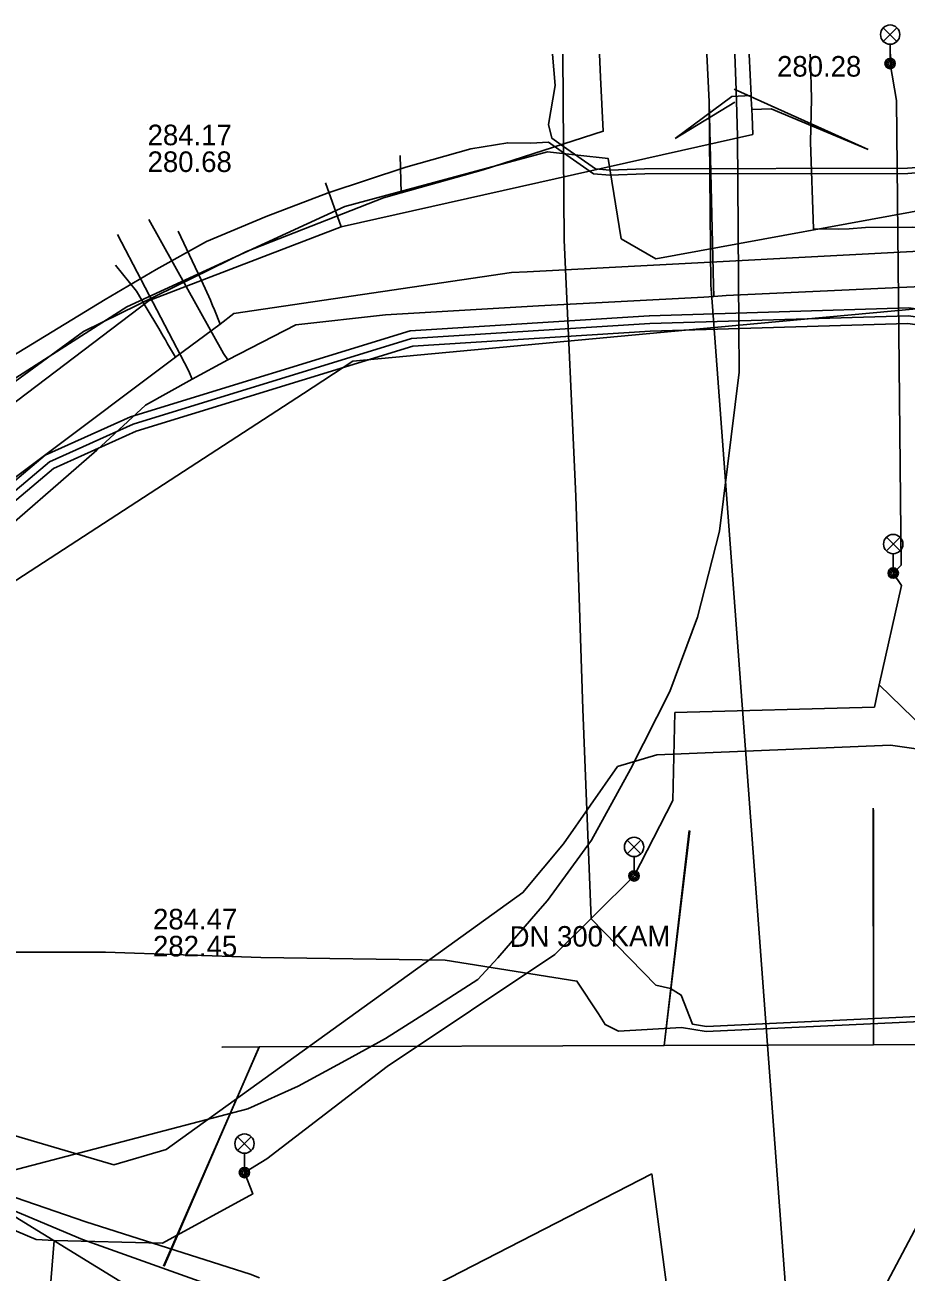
# Model space of a CAD drawing. Extents: x -599854 to -599675, y -1160809 to -1160543.
# Drawn here: x -599799.9 to -599765.66, y -1160591.29 to -1160542.82 of the extents above; entities that cross this region are included whole.
import ezdxf

# ---------------------------------------------------------------- set-up
doc = ezdxf.new("R2010")
doc.units = 0
for name, color, linetype in [('BKOM-ODVODNENI_trasa sítě', 7, 'Continuous'), ('BVK-JEDNOTNA_popisy', 7, 'Continuous'), ('BVK-JEDNOTNA_trasa sítě', 7, 'Continuous'), ('BVK-KANALIZACE_ vyřazená trasa sítě', 7, 'Continuous'), ('BVK-VODOVOD_trasa sítě', 7, 'Continuous'), ('BVK-VODOVOD_trasa zrušené sítě', 7, 'Continuous'), ('CETIN_kabel podzemní', 7, 'Continuous'), ('CETIN_kabel podzemní neprovozovaný', 7, 'Continuous'), ('DESTOVA-NEPROVOZOVANA_popisy', 7, 'Continuous'), ('DESTOVA_trasa neprovozované sítě', 7, 'Continuous'), ('DPMB_kabel', 7, 'Continuous'), ('DPMB_kyneta', 7, 'Continuous'), ('DPMB_trolejové vedení-nosné lano', 7, 'Continuous'), ('DSP-JEDNOTNA-BVK_trasa sítě', 7, 'Continuous'), ('EON-NN_kabel', 7, 'Continuous'), ('EON-NN_kabel zrušené sítě', 7, 'Continuous'), ('INNOGY-NTL_trasa sítě', 7, 'Continuous'), ('INNOGY-STL_trasa sítě', 7, 'Continuous'), ('JEDNOTNA-NEPR_popisy', 7, 'Continuous'), ('JEDNOTNA_trasa neprovozované sítě', 7, 'Continuous'), ('TSB_kabel VO', 7, 'Continuous'), ('TSB_lampy VO', 7, 'Continuous')]:
    doc.layers.add(name, color=color, linetype=linetype)

msp = doc.modelspace()

# ---------------------------------------------------------------- linework, layer by layer
at = {"layer": 'BKOM-ODVODNENI_trasa sítě'}
for points in [[(-599767.13, -1160547.66), (-599772.336, -1160545.322)], [(-599774.63, -1160547.23), (-599772.315, -1160545.821)], [(-599766.926, -1160573.322), (-599766.92, -1160582.45)], [(-599774.061, -1160574.134), (-599775.06, -1160582.48)], [(-599792.21, -1160582.54), (-599790.8, -1160582.535), (-599775.06, -1160582.479), (-599766.92, -1160582.451), (-599752.61, -1160582.4)], [(-599794.512, -1160591.061), (-599790.8, -1160582.54)]]:
    msp.add_lwpolyline(points, dxfattribs=at)
at = {"layer": 'BVK-JEDNOTNA_trasa sítě'}
msp.add_lwpolyline([(-599771.61, -1160547.08), (-599771.647, -1160546.364), (-599771.66, -1160546.11), (-599771.675, -1160545.698), (-599771.68, -1160545.56), (-599771.7591, -1160543.9495)], dxfattribs=at)
at = {"layer": 'BVK-KANALIZACE_ vyřazená trasa sítě'}
for points in [[(-599772.213, -1160547.139), (-599772.256, -1160545.785), (-599772.269, -1160545.352), (-599772.3132, -1160543.9495)], [(-599781.529, -1160579.068), (-599779.972, -1160577.276), (-599779.597, -1160576.845), (-599777.887, -1160574.498), (-599776.366, -1160571.74), (-599774.84, -1160568.724), (-599773.766, -1160565.837), (-599772.907, -1160562.49), (-599772.14, -1160556.317), (-599772.154, -1160554.529), (-599772.199, -1160548.939), (-599772.213, -1160547.139)], [(-599822.796, -1160585.73), (-599821.384, -1160585.908), (-599811.025, -1160587.485), (-599805.422, -1160587.8), (-599801.54, -1160587.634), (-599791.243, -1160584.941), (-599789.279, -1160584.062), (-599787.442, -1160583.059), (-599785.884, -1160582.21), (-599784.335, -1160581.226), (-599782.303, -1160579.92), (-599781.529, -1160579.068)]]:
    msp.add_lwpolyline(points, dxfattribs=at)
at = {"layer": 'BVK-VODOVOD_trasa sítě'}
for p, q in [((-599773.15, -1160552.95), (-599773.31, -1160545.81)), ((-599773.129, -1160553.369), (-599773.52, -1160553.4)), ((-599773.129, -1160553.369), (-599773.15, -1160552.95)), ((-599772.65, -1160553.34), (-599773.129, -1160553.369))]:
    msp.add_line(p, q, dxfattribs=at)
for points in [[(-599773.31, -1160545.81), (-599773.406, -1160543.9495)], [(-599792.01, -1160555.84), (-599792.18, -1160555.59), (-599795.084, -1160550.381)], [(-599793.4, -1160556.58), (-599793.55, -1160556.25), (-599796.307, -1160550.968)], [(-599719.633, -1160602.967), (-599720.5, -1160603.21), (-599721.46, -1160603.05), (-599723.09, -1160601.91), (-599724.27, -1160595.77), (-599725.34, -1160590.19), (-599725.75, -1160588.02), (-599726.33, -1160585.11), (-599727.19, -1160580.77), (-599730.66, -1160575.71), (-599731.23, -1160574.92), (-599731.73, -1160574.22), (-599732.69, -1160572.85), (-599736.99, -1160566.71), (-599739.23, -1160561.6), (-599744.81, -1160557.63), (-599749.37, -1160554.46), (-599750.43, -1160553.69), (-599750.93, -1160553.31), (-599752.19, -1160552.51), (-599757.77, -1160552.65), (-599772.65, -1160553.34)], [(-599773.52, -1160553.4), (-599779.95, -1160553.74), (-599785.89, -1160554.08), (-599789.37, -1160554.47), (-599792.01, -1160555.84), (-599793.4, -1160556.58), (-599795.21, -1160557.59), (-599797.11, -1160559.34), (-599801.61, -1160563.26), (-599803.76, -1160565.39), (-599806.64, -1160570.9), (-599807.42, -1160572.3), (-599808.48, -1160574.16), (-599810.38, -1160577.75), (-599811.83, -1160580.4), (-599815.36, -1160586.95)]]:
    msp.add_lwpolyline(points, dxfattribs=at)
at = {"layer": 'BVK-VODOVOD_trasa zrušené sítě'}
for points in [[(-599773.31, -1160545.81), (-599773.4008, -1160543.9495)], [(-599769.661, -1160601.069), (-599773.22, -1160553.25), (-599773.248, -1160552.933), (-599773.31, -1160545.81)], [(-599723.312, -1160596.189), (-599723.552, -1160595.075), (-599725.385, -1160585.124), (-599727.088, -1160577.648), (-599730.061, -1160573.561), (-599730.185, -1160573.396), (-599730.663, -1160572.731), (-599734.747, -1160567.144), (-599747.147, -1160556.314), (-599750.794, -1160554.698), (-599754.863, -1160552.892), (-599773.118, -1160554.584), (-599787.156, -1160555.886), (-599789.075, -1160557.142), (-599798.149, -1160563.04), (-599806.144, -1160568.237), (-599808.168, -1160571.846), (-599815.66, -1160586.425), (-599816.228, -1160587.481)]]:
    msp.add_lwpolyline(points, dxfattribs=at)
at = {"layer": 'CETIN_kabel podzemní'}
for points in [[(-599760.54, -1160548.25), (-599763.79, -1160549.79), (-599775.39, -1160551.91), (-599776.73, -1160551.13), (-599777.24, -1160548.01), (-599779.6, -1160547.75), (-599787.47, -1160549.87), (-599795.94, -1160553.78), (-599800.44, -1160556.65), (-599809.68, -1160565.19), (-599817.48, -1160577.77), (-599818.39, -1160579.19)], [(-599814.4, -1160581.07), (-599811.3, -1160581.33), (-599803.39, -1160585.07), (-599799.44, -1160586.24), (-599796.45, -1160587.12), (-599794.41, -1160586.52), (-599780.55, -1160576.54), (-599778.97, -1160574.64), (-599776.87, -1160571.64), (-599775.34, -1160571.18), (-599766.27, -1160570.81), (-599760.94, -1160571.57), (-599759.27, -1160573.58), (-599754.54, -1160576.32), (-599750.34, -1160581.07), (-599747.4, -1160585.47), (-599742.37, -1160594.32)]]:
    msp.add_lwpolyline(points, dxfattribs=at)
at = {"layer": 'CETIN_kabel podzemní neprovozovaný'}
for points in [[(-599785.28, -1160549.34), (-599782.1, -1160548.45), (-599777.43, -1160546.95), (-599777.53, -1160544.85), (-599777.5746, -1160543.9495)], [(-599785.32, -1160547.9), (-599785.28, -1160549.34)], [(-599785.97, -1160549.54), (-599785.28, -1160549.34)], [(-599806.6, -1160561.96), (-599804.15, -1160559.5), (-599797.63, -1160554.73), (-599791.29, -1160551.62), (-599785.97, -1160549.54)], [(-599812.02, -1160583.41), (-599810.64, -1160583.64), (-599808.92, -1160584.27), (-599805.91, -1160586), (-599802.25, -1160587.71), (-599797.54, -1160589.34), (-599791.15, -1160591.37), (-599790.79, -1160591.51)], [(-599811.253, -1160583.779), (-599802.42, -1160588.03), (-599797.67, -1160590.02), (-599791.5, -1160592.22), (-599791.17, -1160592.27)]]:
    msp.add_lwpolyline(points, dxfattribs=at)
at = {"layer": 'DESTOVA-NEPROVOZOVANA_popisy'}
msp.add_line((-599794.923, -1160579.019), (-599794.923, -1160579.019), dxfattribs=at)
at = {"layer": 'DESTOVA_trasa neprovozované sítě'}
for p, q in [((-599788.22, -1160548.96), (-599787.61, -1160550.66)), ((-599766.94, -1160573.26), (-599766.92, -1160582.451)), ((-599774.09, -1160574.12), (-599775.06, -1160582.479)), ((-599794.49, -1160591.06), (-599790.8, -1160582.535))]:
    msp.add_line(p, q, dxfattribs=at)
for points in [[(-599774.63, -1160547.23), (-599772.433, -1160545.599), (-599771.68, -1160545.56)], [(-599767.13, -1160547.66), (-599770.908, -1160546.077), (-599771.66, -1160546.11)], [(-599792.25, -1160582.55), (-599790.8, -1160582.535), (-599775.06, -1160582.479), (-599766.92, -1160582.451), (-599752.61, -1160582.4)]]:
    msp.add_lwpolyline(points, dxfattribs=at)
at = {"layer": 'DPMB_kabel'}
for points in [[(-599742.967, -1160562.458), (-599745.93, -1160559.394), (-599753.706, -1160555.543), (-599765.553, -1160553.819), (-599775.629, -1160554.12), (-599775.639, -1160554.121), (-599784.934, -1160554.703), (-599795.796, -1160558.049), (-599799.111, -1160559.544), (-599805.518, -1160564.943)], [(-599742.967, -1160562.458), (-599745.93, -1160559.394), (-599753.706, -1160555.543), (-599765.553, -1160553.819), (-599775.629, -1160554.12), (-599775.639, -1160554.121), (-599784.934, -1160554.703), (-599795.796, -1160558.049), (-599799.111, -1160559.544), (-599805.518, -1160564.943)], [(-599854.3744, -1160570.8811), (-599853.98, -1160571.11), (-599853.34, -1160571.94), (-599850.41, -1160575.09), (-599849.54, -1160575.55), (-599841.94, -1160567.75), (-599841.46, -1160567.86), (-599836.83, -1160571.43), (-599830.31, -1160574.99), (-599826.68, -1160574.81), (-599821.59, -1160577.6), (-599817.92, -1160579.72), (-599816.48, -1160579.55), (-599815.751, -1160578.652), (-599810.91, -1160571.26), (-599805.31, -1160565.16), (-599798.95, -1160559.8), (-599795.69, -1160558.33), (-599784.88, -1160555), (-599775.62, -1160554.42), (-599765.57, -1160554.12), (-599753.796, -1160555.833), (-599746.11, -1160559.64), (-599743.15, -1160562.7)], [(-599854.3744, -1160570.8811), (-599853.98, -1160571.11), (-599853.34, -1160571.94), (-599850.41, -1160575.09), (-599849.54, -1160575.55), (-599841.94, -1160567.75), (-599841.46, -1160567.86), (-599836.83, -1160571.43), (-599830.31, -1160574.99), (-599826.68, -1160574.81), (-599821.59, -1160577.6), (-599817.92, -1160579.72), (-599816.48, -1160579.55), (-599815.751, -1160578.652), (-599810.91, -1160571.26), (-599805.31, -1160565.16), (-599798.95, -1160559.8), (-599795.69, -1160558.33), (-599784.88, -1160555), (-599775.62, -1160554.42), (-599765.57, -1160554.12), (-599753.796, -1160555.833), (-599746.11, -1160559.64), (-599743.15, -1160562.7)]]:
    msp.add_lwpolyline(points, dxfattribs=at)
at = {"layer": 'DPMB_kyneta'}
for points in [[(-599775.601, -1160554.719), (-599784.826, -1160555.297), (-599795.584, -1160558.611), (-599798.789, -1160560.056), (-599805.102, -1160565.377), (-599810.672, -1160571.445), (-599815.508, -1160578.829), (-599816.324, -1160579.834), (-599817.984, -1160580.03), (-599821.737, -1160577.861), (-599826.75, -1160575.114), (-599830.38, -1160575.294), (-599836.994, -1160571.682), (-599841.591, -1160568.138), (-599841.843, -1160568.08), (-599849.482, -1160575.92), (-599850.595, -1160575.331), (-599853.569, -1160572.134), (-599854.182, -1160571.34), (-599854.3744, -1160571.2283)], [(-599679.2237, -1160588.7865), (-599682.09, -1160589.515), (-599685.576, -1160587.065), (-599686.493, -1160586.917), (-599689.402, -1160587.72), (-599697.166, -1160589.741), (-599712.717, -1160593.601), (-599718.397, -1160595.039), (-599721.496, -1160595.147), (-599723.319, -1160593.689), (-599724.625, -1160587.968), (-599724.995, -1160585.706), (-599726.218, -1160580.085), (-599729.152, -1160573.2), (-599732.987, -1160568.044), (-599737.527, -1160565.171), (-599740.396, -1160564.524), (-599743.333, -1160562.942), (-599746.29, -1160559.886), (-599753.886, -1160556.123), (-599765.587, -1160554.421), (-599775.611, -1160554.72)]]:
    msp.add_lwpolyline(points, dxfattribs=at)
at = {"layer": 'DPMB_trolejové vedení-nosné lano'}
for points in [[(-599791.2, -1160594.72), (-599809.14, -1160583.7)], [(-599789.88, -1160594.84), (-599775.54, -1160587.47)], [(-599775.54, -1160587.47), (-599773.84, -1160600.3)]]:
    msp.add_lwpolyline(points, dxfattribs=at)
at = {"layer": 'DSP-JEDNOTNA-BVK_trasa sítě'}
for p, q in [((-599772.433, -1160545.599), (-599771.684, -1160545.563)), ((-599770.908, -1160546.077), (-599771.657, -1160546.112)), ((-599766.94, -1160573.26), (-599766.92, -1160582.451)), ((-599774.09, -1160574.12), (-599775.06, -1160582.479)), ((-599790.8, -1160582.535), (-599775.06, -1160582.479)), ((-599775.06, -1160582.479), (-599766.92, -1160582.451)), ((-599766.92, -1160582.451), (-599752.61, -1160582.4)), ((-599794.49, -1160591.06), (-599790.8, -1160582.535)), ((-599792.21, -1160582.54), (-599790.8, -1160582.535))]:
    msp.add_line(p, q, dxfattribs=at)
at = {"layer": 'EON-NN_kabel'}
for points in [[(-599779.292, -1160545.175), (-599779.3939, -1160543.9495)], [(-599762.627, -1160545.843), (-599762.668, -1160546.074), (-599762.734, -1160546.449), (-599762.827, -1160546.981), (-599763.401, -1160547.905), (-599764.06, -1160548.272), (-599764.861, -1160548.333), (-599765.604, -1160548.39), (-599775.822, -1160548.41), (-599777.168, -1160548.46), (-599777.735, -1160548.413), (-599778.972, -1160547.542), (-599779.425, -1160547.223), (-599779.55, -1160546.69), (-599779.292, -1160545.175)], [(-599762.43, -1160545.88), (-599762.48, -1160546.163), (-599762.636, -1160547.054), (-599763.259, -1160548.055), (-599764, -1160548.468), (-599764.843, -1160548.532), (-599765.596, -1160548.59), (-599775.818, -1160548.61), (-599777.172, -1160548.66), (-599777.805, -1160548.607), (-599778.97, -1160547.788), (-599779.554, -1160547.378), (-599780.24, -1160547.41), (-599781.14, -1160547.4), (-599782.57, -1160547.64), (-599785.1, -1160548.35), (-599788.12, -1160549.35), (-599790.53, -1160550.26), (-599792.84, -1160551.23), (-599794.8, -1160552.33), (-599796.78, -1160553.49), (-599801.45, -1160556.33)]]:
    msp.add_lwpolyline(points, dxfattribs=at)
at = {"layer": 'EON-NN_kabel zrušené sítě'}
for points in [[(-599778.9929, -1160543.9495), (-599778.972, -1160547.542), (-599778.97, -1160547.788), (-599778.95, -1160551.18), (-599778.49, -1160561.13), (-599778.22, -1160569.41), (-599777.9, -1160577.56), (-599775.38, -1160580.14), (-599774.82, -1160580.27), (-599774.4, -1160580.52), (-599773.962, -1160581.651), (-599773.414, -1160581.74), (-599764.965, -1160581.343), (-599764.621, -1160580.237), (-599764.322, -1160579.771), (-599762.931, -1160579.512), (-599762.188, -1160579.659), (-599761.325, -1160579.531)], [(-599761.295, -1160579.729), (-599762.192, -1160579.861), (-599762.969, -1160579.708), (-599764.198, -1160579.949), (-599764.439, -1160580.323), (-599764.815, -1160581.537), (-599773.426, -1160581.94), (-599774.387, -1160581.787), (-599776.84, -1160581.93), (-599777.35, -1160581.67), (-599777.61, -1160581.25), (-599778.45, -1160579.98), (-599783.57, -1160579.17), (-599790.74, -1160579.06), (-599796.77, -1160578.86), (-599802.11, -1160578.86)]]:
    msp.add_lwpolyline(points, dxfattribs=at)
at = {"layer": 'INNOGY-NTL_trasa sítě'}
for points in [[(-599769.3869, -1160543.9495), (-599769.379, -1160544.191), (-599769.33, -1160545.69), (-599769.376, -1160547.382), (-599769.259, -1160550.742), (-599768.28, -1160550.753)], [(-599762.899, -1160550.371), (-599762.79, -1160550.72), (-599764.29, -1160550.8), (-599765.418, -1160550.679), (-599767.231, -1160550.694), (-599767.869, -1160550.747), (-599768.28, -1160550.753)]]:
    msp.add_lwpolyline(points, dxfattribs=at)
at = {"layer": 'INNOGY-STL_trasa sítě'}
for points in [[(-599792.31, -1160554.45), (-599792.54, -1160553.89), (-599792.59, -1160553.78), (-599792.6, -1160553.76), (-599792.69, -1160553.52), (-599793.04, -1160552.75), (-599793.4, -1160551.99), (-599793.95, -1160550.84)], [(-599761.73, -1160551.43), (-599762.21, -1160551.46), (-599780.39, -1160552.41), (-599780.99, -1160552.44)], [(-599794.05, -1160555.73), (-599794.36, -1160555.21), (-599794.44, -1160555.06), (-599794.53, -1160554.92), (-599794.7, -1160554.62), (-599795.19, -1160553.8), (-599795.57, -1160553.17), (-599796.38, -1160552.15)], [(-599780.99, -1160552.44), (-599791.78, -1160554.03), (-599792.31, -1160554.45), (-599794.05, -1160555.73), (-599804.4, -1160563.49), (-599804.53, -1160563.48), (-599804.66, -1160563.47), (-599805.49, -1160563.4), (-599806.68, -1160563.29), (-599806.84, -1160563.28), (-599811.27, -1160567.47), (-599811.2, -1160567.91), (-599811.17, -1160568.07), (-599811.12, -1160568.36), (-599810.84, -1160570.05), (-599810.7, -1160570.94), (-599810.69, -1160571.01), (-599810.61, -1160571.46), (-599810.57, -1160571.72), (-599813.95, -1160577.93), (-599814.51, -1160578.96)]]:
    msp.add_lwpolyline(points, dxfattribs=at)
at = {"layer": 'JEDNOTNA-NEPR_popisy'}
msp.add_line((-599795.134, -1160546.695), (-599795.134, -1160546.695), dxfattribs=at)
at = {"layer": 'JEDNOTNA_trasa neprovozované sítě'}
msp.add_line((-599787.61, -1160550.66), (-599771.61, -1160547.08), dxfattribs=at)
msp.add_lwpolyline([(-599802.92, -1160559.49), (-599800.171, -1160557.403), (-599795.07, -1160553.53), (-599787.61, -1160550.66)], dxfattribs=at)
at = {"layer": 'TSB_kabel VO'}
for points in [[(-599766.2621, -1160543.9495), (-599766.24, -1160544.4)], [(-599766.28, -1160544.32), (-599766.03, -1160545.76), (-599765.85, -1160563.81), (-599766.16, -1160564.12), (-599765.84, -1160564.6), (-599766.71, -1160568.47)], [(-599854.3744, -1160555.1902), (-599854.04, -1160555.5), (-599849.6, -1160560.93), (-599846.5, -1160564.23), (-599842.34, -1160567.41), (-599836.14, -1160572.72), (-599835.53, -1160572.87), (-599830.9, -1160574.94), (-599826.66, -1160576.79), (-599812.72, -1160583.91), (-599805.44, -1160587.49), (-599799.47, -1160590.02), (-599798.76, -1160590.06), (-599794.55, -1160590.16), (-599791.05, -1160588.25), (-599791.37, -1160587.42), (-599790.5, -1160586.88), (-599785.83, -1160583.3), (-599779.31, -1160578.94), (-599776.23, -1160575.89), (-599774.72, -1160572.96), (-599774.64, -1160569.54), (-599766.89, -1160569.33), (-599766.71, -1160568.47)], [(-599766.71, -1160568.47), (-599766.89, -1160569.33), (-599774.64, -1160569.54), (-599774.72, -1160572.96), (-599776.23, -1160575.89), (-599779.31, -1160578.94), (-599785.83, -1160583.3), (-599790.5, -1160586.88), (-599791.37, -1160587.42), (-599791.05, -1160588.25), (-599794.55, -1160590.16), (-599798.76, -1160590.06), (-599799.72, -1160601.87), (-599800.78, -1160601.67)], [(-599766.71, -1160568.47), (-599762.32, -1160572.73), (-599758.16, -1160577.35), (-599760.07, -1160579.7), (-599764.277, -1160587.66), (-599769.44, -1160597.43)], [(-599712.85, -1160612.2), (-599713.231, -1160610.818), (-599715.05, -1160611.32), (-599720.13, -1160612.91), (-599729.8, -1160616.03), (-599730.26, -1160617.21), (-599734.33, -1160617.68), (-599739.29, -1160617.63), (-599739.48, -1160618.61), (-599740.14, -1160618.47), (-599744.95, -1160617.17), (-599744.01, -1160615.53), (-599741.64, -1160607.33), (-599740.03, -1160599.74), (-599742.84, -1160597.94), (-599743.59, -1160597.21), (-599749.46, -1160587.62), (-599756.62, -1160578.69), (-599758.16, -1160577.35), (-599762.32, -1160572.73), (-599766.71, -1160568.47)]]:
    msp.add_lwpolyline(points, dxfattribs=at)
at = {"layer": 'TSB_lampy VO'}
for p, q in [((-599766.545, -1160543.46), (-599766.015, -1160542.93)), ((-599766.545, -1160542.93), (-599766.015, -1160543.46)), ((-599766.545, -1160543.46), (-599766.015, -1160542.93)), ((-599766.545, -1160542.93), (-599766.015, -1160543.46)), ((-599766.28, -1160543.57), (-599766.28, -1160544.32)), ((-599766.28, -1160543.57), (-599766.28, -1160544.32)), ((-599766.425, -1160563.26), (-599765.895, -1160562.73)), ((-599766.425, -1160562.73), (-599765.895, -1160563.26)), ((-599766.425, -1160563.26), (-599765.895, -1160562.73)), ((-599766.425, -1160562.73), (-599765.895, -1160563.26)), ((-599766.16, -1160563.37), (-599766.16, -1160564.12)), ((-599766.16, -1160563.37), (-599766.16, -1160564.12)), ((-599776.495, -1160575.03), (-599775.965, -1160574.5)), ((-599776.495, -1160574.5), (-599775.965, -1160575.03)), ((-599776.495, -1160575.03), (-599775.965, -1160574.5)), ((-599776.495, -1160574.5), (-599775.965, -1160575.03)), ((-599776.23, -1160575.14), (-599776.23, -1160575.89)), ((-599776.23, -1160575.14), (-599776.23, -1160575.89)), ((-599791.635, -1160586.56), (-599791.105, -1160586.03)), ((-599791.635, -1160586.03), (-599791.105, -1160586.56)), ((-599791.635, -1160586.56), (-599791.105, -1160586.03)), ((-599791.635, -1160586.03), (-599791.105, -1160586.56)), ((-599791.37, -1160586.67), (-599791.37, -1160587.42)), ((-599791.37, -1160586.67), (-599791.37, -1160587.42))]:
    msp.add_line(p, q, dxfattribs=at)
for centre, radius in [((-599766.28, -1160543.195), 0.375), ((-599766.28, -1160543.195), 0.375), ((-599766.28, -1160544.32), 0.2), ((-599766.28, -1160544.32), 0.2), ((-599766.28, -1160544.32), 0.1445), ((-599766.28, -1160544.32), 0.1445), ((-599766.28, -1160544.32), 0.0876), ((-599766.28, -1160544.32), 0.0876), ((-599766.16, -1160562.995), 0.375), ((-599766.16, -1160562.995), 0.375), ((-599766.16, -1160564.12), 0.2), ((-599766.16, -1160564.12), 0.2), ((-599766.16, -1160564.12), 0.1445), ((-599766.16, -1160564.12), 0.1445), ((-599766.16, -1160564.12), 0.0876), ((-599766.16, -1160564.12), 0.0876), ((-599776.23, -1160574.765), 0.375), ((-599776.23, -1160574.765), 0.375), ((-599776.23, -1160575.89), 0.2), ((-599776.23, -1160575.89), 0.2), ((-599776.23, -1160575.89), 0.1445), ((-599776.23, -1160575.89), 0.1445), ((-599776.23, -1160575.89), 0.0876), ((-599776.23, -1160575.89), 0.0876), ((-599791.37, -1160586.295), 0.375), ((-599791.37, -1160586.295), 0.375), ((-599791.37, -1160587.42), 0.2), ((-599791.37, -1160587.42), 0.2), ((-599791.37, -1160587.42), 0.1445), ((-599791.37, -1160587.42), 0.1445), ((-599791.37, -1160587.42), 0.0876), ((-599791.37, -1160587.42), 0.0876)]:
    msp.add_circle(centre, radius, dxfattribs=at)

# ---------------------------------------------------------------- texts
at = {"layer": 'BVK-JEDNOTNA_popisy'}
msp.add_text('280.28', height=0.8, dxfattribs=at).set_placement((-599770.673, -1160544.828))
at = {"layer": 'DESTOVA-NEPROVOZOVANA_popisy'}
for s, p in [('284.47', (-599794.923, -1160577.969)), ('282.45', (-599794.923, -1160579.019))]:
    msp.add_text(s, height=0.8, dxfattribs=at).set_placement(p)
msp.add_text('DN 300 KAM', height=0.8, rotation=0.20256, dxfattribs=at).set_placement((-599781.064, -1160578.648))
at = {"layer": 'JEDNOTNA-NEPR_popisy'}
for s, p in [('284.17', (-599795.134, -1160547.495)), ('280.68', (-599795.134, -1160548.535))]:
    msp.add_text(s, height=0.8, dxfattribs=at).set_placement(p)

doc.saveas('drawing.dxf')
